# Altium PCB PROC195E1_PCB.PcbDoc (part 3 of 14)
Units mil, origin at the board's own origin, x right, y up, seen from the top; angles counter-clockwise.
Board outline 3110.24 x 2500 mil, 10 copper layers (Top Layer, L02_GND1, L03_SIG1, L04_GND2, L05_PWR1, L06_PWR2, L07_GND3, L08_SIG2, L09_GND4, Bottom Layer), stack 66.407 mil thick; 571 components, 538 nets, 6726 pads, 1286 vias.
Unrouted connection lines stored in the file: 4.
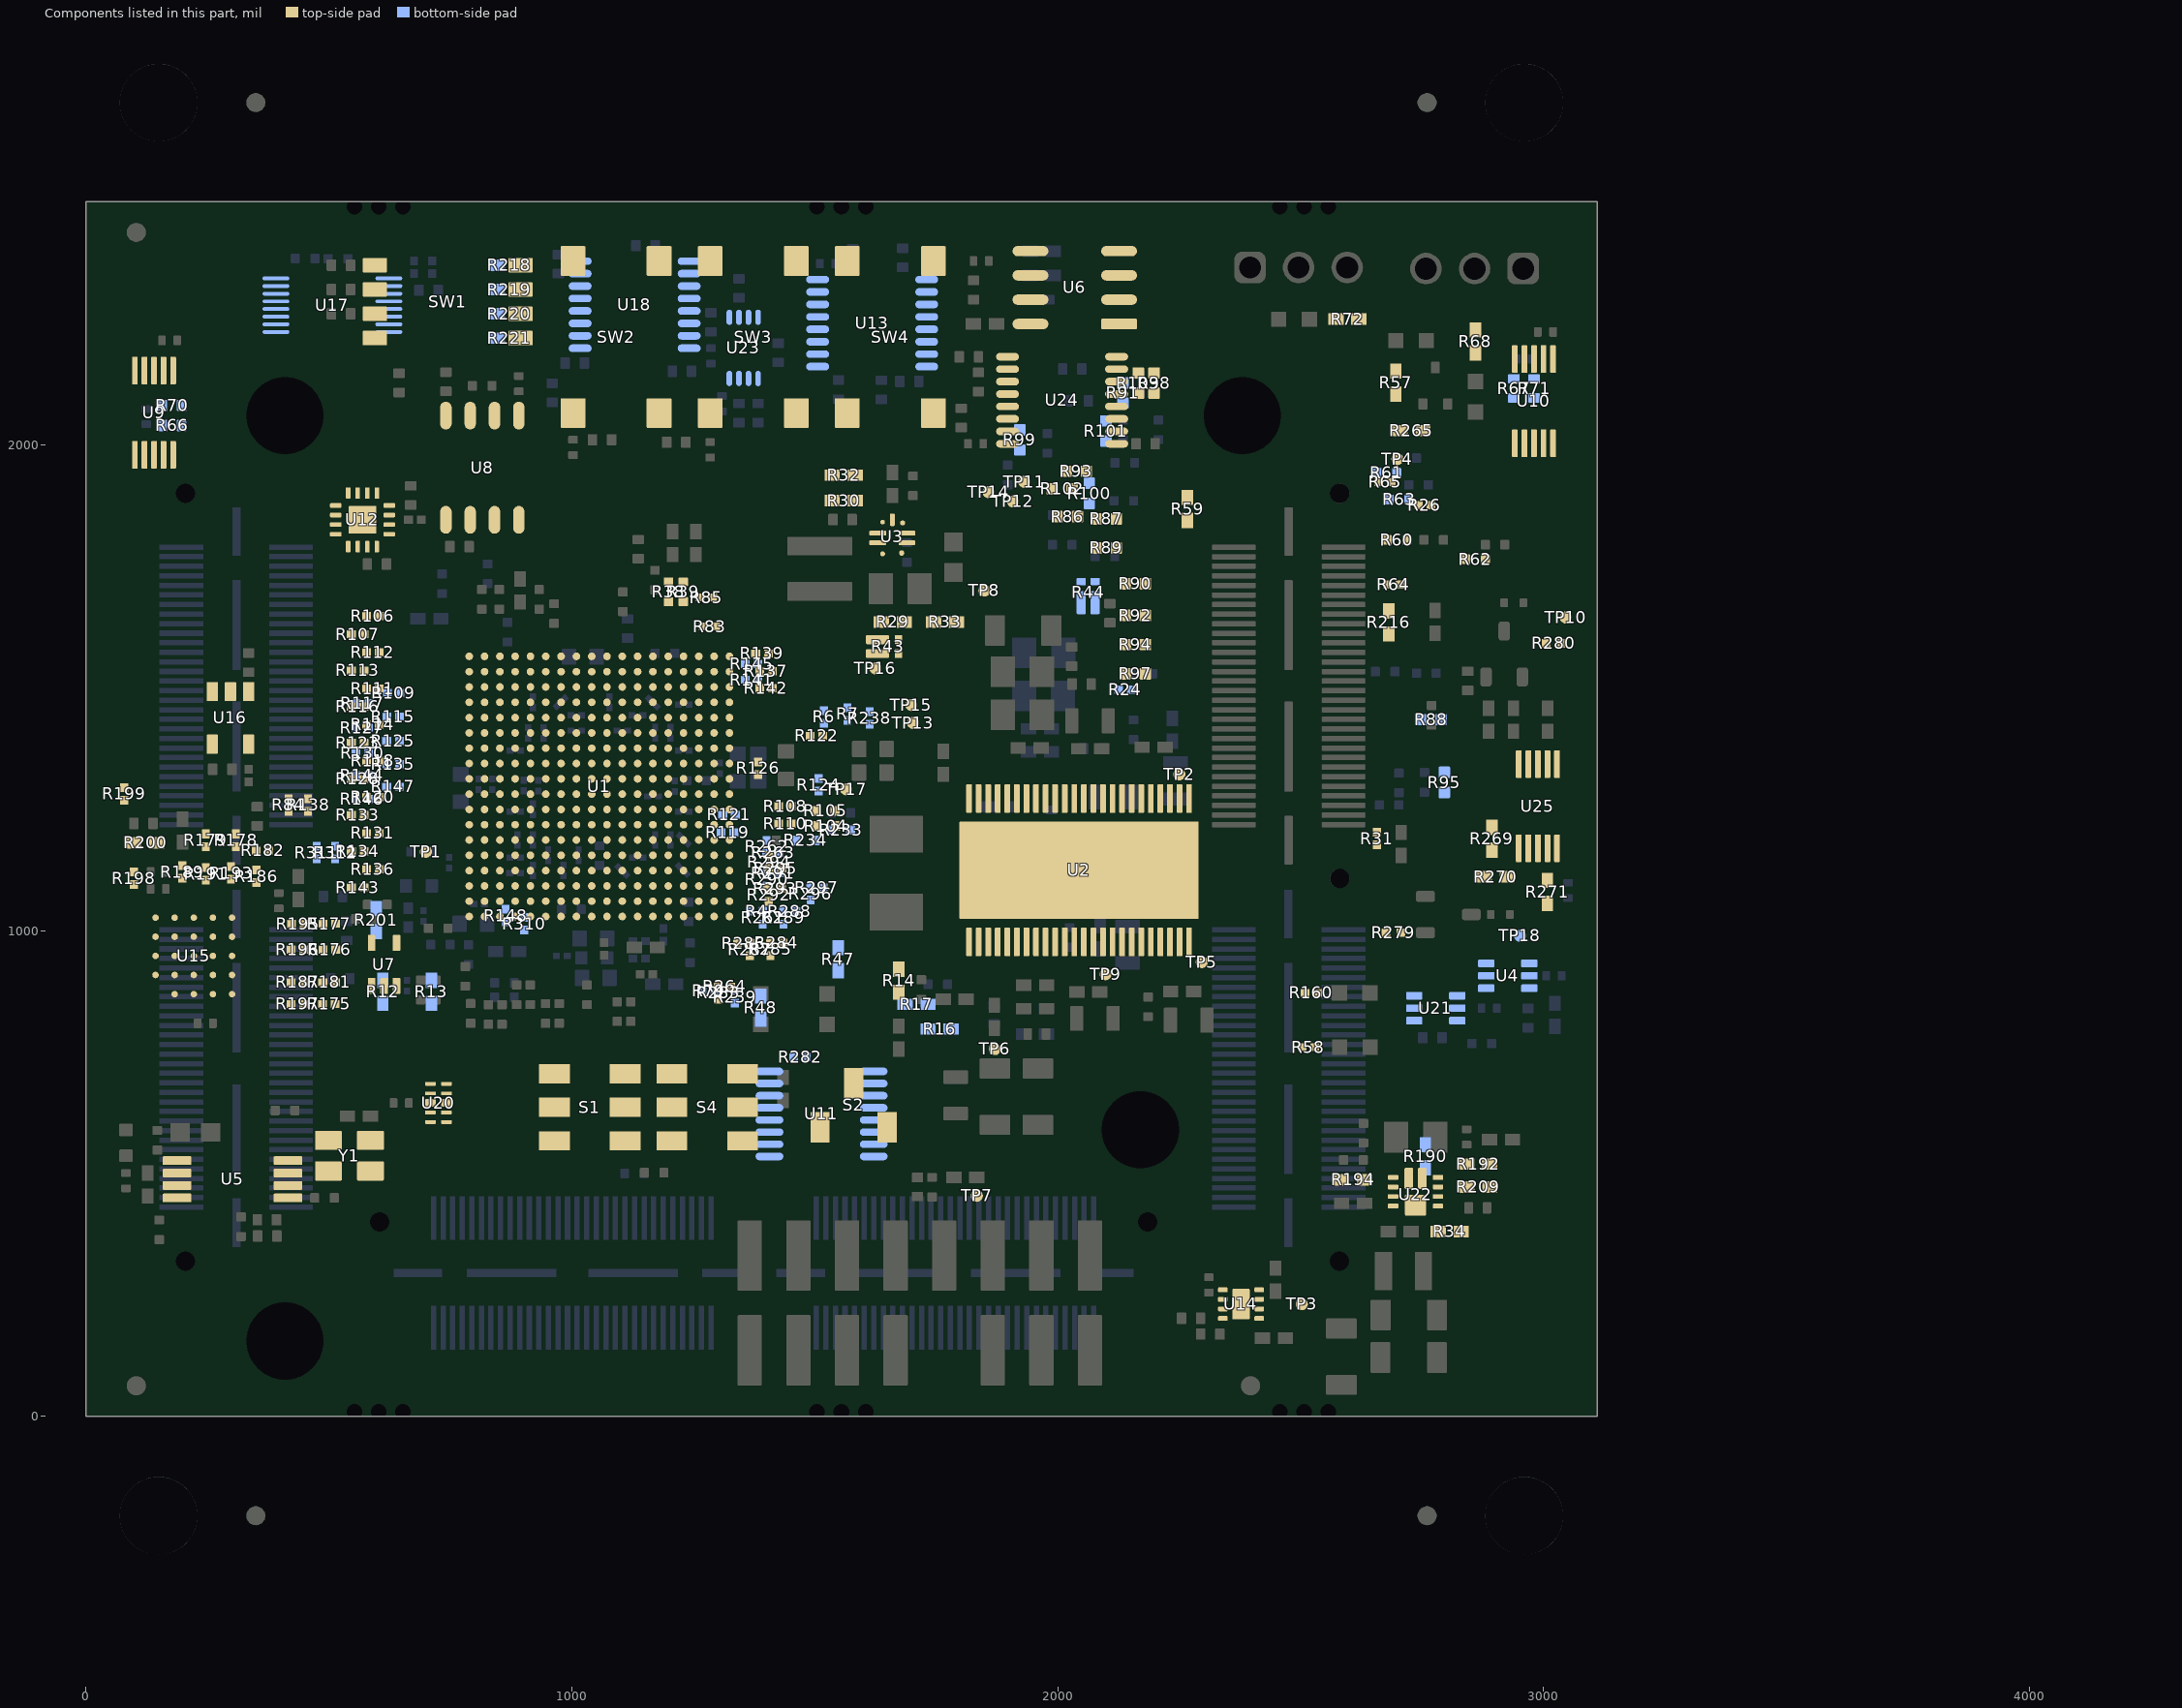
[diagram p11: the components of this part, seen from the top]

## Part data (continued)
R4 R6 R7 R26 R31 R64 R79 R83 R84 R85 R108 R110 R119 R121 R122 R124 R126 R137 R138 R139 R141 R142 R145 R148 R199 R238 R239 R261 R262 R263 R264 R282 R283 R284 R285 R286 R287 R288 R289 R290 R291 R292 R293 R294 R295 R296 R297 R310 R311 R312: library part CMP-0065361-1, "RES, 0, 5%, .05 W, AEC-Q200 Grade 0, 0201", Manufacturer=Panasonic, Power_W=50mW, Supplier Part Number 1=P15979CT-ND, TempCo=ppm/C, Tolerance_%=5%, Value2=.05W, Value_Code=0000, ValueDisplayed=0
R12 R16 R29 R33 R271: library part CMP-0077731-1, "RES, 10.0 k, 1%, 0.063 W, AEC-Q200 Grade 0, 0402", Manufacturer="Yageo America", Power_W=63mW, Supplier Part Number 1=YAG3436CT-ND, TempCo="100 ppm/C", Tolerance_%=1%, Value2=0.063W, Value_Code=10k0, ValueDisplayed=10.0k
R13: library part CMP-0026240-2, "RES, 2.67 k, 1%, 0.063 W, AEC-Q200 Grade 0, 0402", Manufacturer=Vishay-Dale, Power_W=63mW, Supplier Part Number 1=541-2.67KLCT-ND, TempCo="100 ppm/C", Tolerance_%=1%, Value2=0.063W, Value_Code=2k67, ValueDisplayed=2.67k
R14: library part CMP-0078193-1, "RES, 1.0 k, 5%, 0.1 W, AEC-Q200 Grade 0, 0402", Manufacturer=Panasonic, Power_W=100mW, Supplier Part Number 1=P1.0KJCT-ND, TempCo="200 ppm/C", Tolerance_%=5%, Value2=0.1W, Value_Code=1k00, ValueDisplayed=1.0k
R17: library part CMP-0026920-5, "RES, 3.9 k, 5%, 0.063 W, AEC-Q200 Grade 0, 0402", Manufacturer=Vishay-Dale, Power_W=63mW, Supplier Part Number 1=541-3.9KJCT-ND, TempCo="200 ppm/C", Tolerance_%=5%, Value2=0.063W, Value_Code=3k90, ValueDisplayed=3.9k
R24 R65 R106 R107 R109 R111 R112 R113 R114 R115 R116 R117 R118 R120 R123 R125 R127 R128 R130 R131 R133 R134 R135 R136 R143 R144 R146 R147 R186 R187 R189 R191 R193 R195 R196 R197 R198: library part CMP-0027500-1, "RES, 22.0, 1%, 0.05 W, 0201", Manufacturer="Yageo America", Power_W=50mW, Supplier Part Number 1=YAG2518CT-ND, TempCo="200 ppm/C", Tolerance_%=1%, Value2=0.05W, Value_Code=22R0, ValueDisplayed=22.0
R30 R32 R201: library part CMP-0026823-3, "RES, 100 k, 5%, 0.063 W, AEC-Q200 Grade 0, 0402", Manufacturer=Vishay-Dale, Power_W=63mW, Supplier Part Number 1=541-100KJCT-ND, TempCo="200 ppm/C", Tolerance_%=5%, Value2=0.063W, Value_Code=100k
R34: library part CMP-0026280-2, "RES, 301 k, 1%, 0.063 W, AEC-Q200 Grade 0, 0402", Manufacturer=Vishay-Dale, Power_W=63mW, Supplier Part Number 1=541-301KLCT-ND, TempCo="100 ppm/C", Tolerance_%=1%, Value2=0.063W, Value_Code=301k
R38 R39 R60 R61 R62 R63: library part CMP-0122104-1, "33 Ohms ±5% 0.1W, 1/10W Chip Resistor 0402 (1005 Metric) Automotive AEC-Q200 Thick Film", Digikey Part Number=P33JCT-ND, Manufacturer=Panasonic, Mouser Part Number=667-ERJ-2GEJ330X, Operating Temperature Range="-55°C to +155°C", Power_W=100mW, TempCo=200ppm/°C, Tolerance_%=5%
R43 R44: library part CMP-0122058-1, "Res Metal Foil 0306 0.01 Ohm 1% 0.25W(1/4W) ±50ppm/C Epoxy Resin Wide Terminal SMD T/R", Digikey Part Number=FC4L16R010FERCT-ND, Manufacturer=Ohmite, Mouser Part Number=588-FC4L16R010FER, Operating Temperature Range="-40°C to +125°C", Power_W=250mW, TempCo=50ppm/°C, Tolerance_%=1%
R47 R48: library part CMP-0026854-5, "RES, 1.2 k, 5%, 0.063 W, AEC-Q200 Grade 0, 0402", Manufacturer=Vishay-Dale, Power_W=63mW, Supplier Part Number 1=541-1.2KJCT-ND, TempCo="200 ppm/C", Tolerance_%=5%, Value2=0.063W, Value_Code=1k20, ValueDisplayed=1.2k
R57 R68 R72: library part CMP-0025998-3, "RES, 130, 1%, 0.063 W, AEC-Q200 Grade 0, 0402", Manufacturer=Vishay-Dale, Power_W=63mW, Supplier Part Number 1=541-130LCT-ND, TempCo="100 ppm/C", Tolerance_%=1%, Value2=0.063W, Value_Code=130R, ValueDisplayed=130
R58 R160: library part CMP-0027222-1, "RES, 300, 5%, 0.05 W, 0201", Manufacturer="Yageo America", Power_W=50mW, Supplier Part Number 1=603-RC0201JR-7D300RL, TempCo="200 ppm/C", Tolerance_%=5%, Value2=0.05W, Value_Code=300R, ValueDisplayed=300
R59 R216: library part CMP-0025951-3, "RES, 100, 1%, 0.063 W, AEC-Q200 Grade 0, 0402", Manufacturer=Vishay-Dale, Power_W=63mW, Supplier Part Number 1=541-100LCT-ND, TempCo="100 ppm/C", Tolerance_%=1%, Value2=0.063W, Value_Code=100R, ValueDisplayed=100
R66 R67 R70 R71: library part CMP-0122043-1, "Res General Purpose Thick Film 0402 10 Ohm 1% 1/16W ±200ppm/°C Molded SMD Paper T/R", Digikey Part Number=311-10.0LRCT-ND, Manufacturer=Yageo, Mouser Part Number=603-RC0402FR-0710RL, Operating Temperature Range="-55°C to +155°C", Power_W=63mW, TempCo=200ppm/°C, Tolerance_%=1%
R86 R87 R88 R89 R90 R91 R92 R93 R94 R95 R97 R98 R99 R100 R101 R102 R103: library part CMP-0097633-1, "10 Ohms ±1% 0.125W, 1/8W Chip Resistor 0402 (1005 Metric) Automotive AEC-Q200 Thick Film", Digikey Part Number=541-RCC040210R0FKEDCT-ND, Manufacturer="Vishay Dale", Mouser Part Number=71-RCC040210R0FKED, Operating Temperature Range="-55°C to +155°C", Power_W=125mW, TempCo=100ppm/°C, Tolerance_%=1%
R104 R105 R233 R234: library part CMP-0042990-1, "Res Thick Film 0402 1.5K Ohm 5% 1/10W ±200ppm/°C Molded SMD Punched Carrier T/R", Digikey Part Number=P1.5KJCT-ND, Manufacturer=Panasonic, Mouser Part Number=667-ERJ-2GEJ152X, Octopart Part Number=cecc048b4d5c110b, Operating Temperature Range="-55°C to +155°C", Power_W=100mW, TempCo=200ppm/°C, Tolerance_%=5%, Voltage=50V
R175 R176 R177 R178 R179 R181 R182: library part CMP-0027732-1, "RES, 49.9 k, 1%, 0.05 W, 0201", Manufacturer="Yageo America", Power_W=50mW, Supplier Part Number 1=YAG2701CT-ND, TempCo="200 ppm/C", Tolerance_%=1%, Value2=0.05W, Value_Code=49k9, ValueDisplayed=49.9k
R190: library part CMP-0026102-2, "RES, 1.05 M, 1%, 0.063 W, AEC-Q200 Grade 0, 0402", Manufacturer=Vishay-Dale, Power_W=63mW, Supplier Part Number 1=541-1.05MLCT-ND, TempCo="100 ppm/C", Tolerance_%=1%, Value2=0.063W, Value_Code=1M05, ValueDisplayed=1.05M
R192: library part CMP-0026187-2, "RES, 23.7 k, 1%, 0.063 W, AEC-Q200 Grade 0, 0402", Manufacturer=Vishay-Dale, Power_W=63mW, Supplier Part Number 1=541-23.7KLCT-ND, TempCo="100 ppm/C", Tolerance_%=1%, Value2=0.063W, Value_Code=23k7, ValueDisplayed=23.7k
R194: library part CMP-0026046-3, "RES, 174 k, 1%, 0.063 W, AEC-Q200 Grade 0, 0402", Manufacturer=Vishay-Dale, Power_W=63mW, Supplier Part Number 1=541-174KLCT-ND, TempCo="100 ppm/C", Tolerance_%=1%, Value2=0.063W, Value_Code=174k
R200 R218 R219 R220 R221 R265 R269 R270: library part CMP-0026657-1, "RES, 1.00 k, 1%, 0.1 W, 0402", Manufacturer=Panasonic, Power_W=100mW, Supplier Part Number 1=P1.00KLCT-ND, TempCo="100 ppm/C", Tolerance_%=1%, Value2=0.1W, Value_Code=1k00, ValueDisplayed=1.00k
R209: library part CMP-0025973-3, "RES, 118 k, 1%, 0.063 W, AEC-Q200 Grade 0, 0402", Manufacturer=Vishay-Dale, Power_W=63mW, Supplier Part Number 1=541-118KLCT-ND, TempCo="100 ppm/C", Tolerance_%=1%, Value2=0.063W, Value_Code=118k
R279 R280: library part CMP-2002-00487-3, "Chip Resistor, 220 Ohm, +/- 5%, 100 mW, -55 to 155 degC, 0402 (1005 Metric), RoHS, Tape and Reel", Case Code (Imperial)=0402, Case Code (Metric)=1005, Manufacturer="Basic Passives", Max Operating Temperature="155 degC", Min Operating Temperature="-55 degC", Package Quantity=10000, Power Rating="100 mW", Resistance="220 Ohm", Tolerance=5%, Voltage Rating="50 V"
S1 S4: library part CMP-0002233-1, "Switch, Dual SPDT,  2 Pos, 0.1A, 6VDC, SMD", CurrentRating_mA=100A, Manufacturer="Copal Electronics", Supplier Part Number 1=CASD20JCT-ND
S2: library part CMP-0002139-2, "Switch, Slide, SPDT  100mA, SMT", CurrentRating_mA=100A, Manufacturer="Copal Electronics", Supplier Part Number 1=CAS120JCT-ND
SW1: library part CMP-0093176-1, "Dip Switch SPST 4 Position Surface Mount Slide (Standard) Actuator 25mA 24VDC", Coil Resistance_ohm=100mΩ, Contact Current Rating=25mA, Digikey Part Number=732-3854-1-ND, Manufacturer=Wurth, Mouser Part Number=710-416131160804, Operating Temperature Range="-40°C to +85°C"
SW2 SW3 SW4: library part CMP-0097324-1, "Switch Tactile N.O. SPST Round Button Gull Wing 0.05A 12VDC 1000000Cycles 1.57N SMD Reel", Coil Resistance_ohm=100mΩ, Contact Current Rating=50mA, Digikey Part Number=732-7005-1-ND, Manufacturer="Wurth Electronics", Mouser Part Number=710-430182050816, Operating Force=160gf, Operating Temperature Range="-40°C to +85°C"
TP1 TP2 TP3 TP4 TP5 TP6 TP7 TP8 TP9 TP10 TP11 TP12 TP13 TP14 TP15 TP16 TP17 TP18: library part CMP-0078143-3, "TEST POINT.  No entry in BOM.", Manufacturer=N/A
U1: library part CMP-0121930-1, Manufacturer="Texas Instruments", Operating Temperature Range=to
U2: library part CMP-0095884-1, "Power Management IC For Safety-Relevant Applications HTSSOP48 5 Outputs 4 LDO and 1 Synchronous Buck-Boost Regulator", Manufacturer="Texas Instruments", Max Supply Voltage=28V, Min Supply Voltage=2.3V, Operating Temperature Range="-40°C to +150°C"
U3: library part CMP-0093448-1, "3-V to 18-V, High Efficiency and Low IQ Buck Converter in QFN HR  Package with 165C Junction temperature", Manufacturer="Texas Instruments", Max Supply Voltage=18V, Min Supply Voltage=3V, Nominal Supply Current=8mA, Operating Temperature Range="-55°C to +165°C", Output Voltage=0.4-5.5V, Switching Frequency=1/2.5MHz
U4 U21: library part CMP-0051216-3, "Single 3-Input Positive-AND Gate, DCK0006A (SOT-SC70-6)", F @ Nom Voltage(Max)(Mhz)=150, Generic Part Number=SN74LVC1G11, ICC @ Nom Voltage(Max)(mA)=0.01, Manufacturer="Texas Instruments", Operating Temperature Range="-40 to 125,-40 to 85 C", Rating=Catalog, tpd @ Nom Voltage(Max)(ns)=20,7.8,6.2,4.6, Voltage(Nom)(V)=1.8,2.5,3.3,5
U5: library part CMP-0096980-1, "1.8-V, 2.5-V, and 3.3-V LVCMOS Clock Buffer Family", Digikey Part Number=296-LMK1C1104PWRCT-ND, Manufacturer="Texas Instruments", Max Supply Voltage=3.465V, Min Supply Voltage=1.71V, Mouser Part Number=595-LMK1C1104PWR, Nominal Supply Current=25-33000uA, Operating Temperature Range="-40°C to +125°C"
U6: library part CMP-0122130-1, "EEPROM Serial-I2C 1M-bit 128K x 8 2.5V/3.3V/5V 8-Pin SOIC N T/R", Digikey Part Number=CAT24M01WI-GT3OSCT-ND, Frequency_Fixed=1MHz, Manufacturer="ON Semi", Max Supply Voltage=5.5V, Min Supply Voltage=1.8V, Mouser Part Number=863-CAT24M01WI-GT3, Nominal Supply Current=1-5mA, Operating Temperature Range="-40°C to +85°C"
U7: library part CMP-0051718-3, "Single Power Supply BUFFER Logic Level Shifter (no enable), DCK0005A (SOT-SC70-5)", F @ Nom Voltage(Max)(Mhz)=50, Generic Part Number=SN74LV1T34, ICC @ Nom Voltage(Max)(mA)=0.01, Manufacturer="Texas Instruments", Operating Temperature Range(C)="-40 to 125", Rating=Catalog, tpd @ Nom Voltage(Max)(ns)=14.5,9.5,8.0,6.5, Voltage(Nom)(V)=1.8,2.5,3.3,5.5
U8: library part CMP-0078516-1, "Remote and Local Temperature Sensor with N-Factor and Series-R Correction in MSOP-8, D0008A (SOIC-8)", Alternate Manufacturer="Texas Instruments", Alternate PartNumber=TMP411AD
U9 U10: library part CMP-0098432-1, "Current Sense Amplifier 1 Circuit 10-VSSOP", Digikey Part Number=296-INA228AIDGSTCT-ND, Input Bias Current=0.01uA, Input Offset Voltage=1mV, Manufacturer="Texas Instruments", Max Supply Voltage=5.5V, Min Supply Voltage=2.7V, Mouser Part Number=595-INA228AIDGST, Nominal Supply Current=640uA, Operating Temperature Range="-40°C to +125°C"
U11: library part CMP-0041147-1, "High-Speed, Single-Supply, Rail-to-Rail Operational Amplifier MicroAmplifier(TM) Series, 2.7 to 5.5 V, -55 to 150 degC, 16-pin SOP (DBQ16), Green (RoHS & no Sb/Br)", Manufacturer="Texas Instruments", Total Supply Voltage(Max)(+5V is 5, +/-5V is 10)=5.5, Total Supply Voltage(Min)(+5V is 5, +/-5V is 10)=2.7
U12: library part CMP-0043157-2, "Low-Voltage 8-Bit I2C and SMBus I/O Expander, 1.65 to 5.5 V, -40 to 85 degC, 16-pin QFN (RGT), Green (RoHS & no Sb/Br)", 5V Tolerant I/O=Yes, Manufacturer="Texas Instruments", Max Frequency(kHz)=400
U13 U18 U24: library part CMP-0076540-1, "4-Bit One-of-2 FET Multiplexer/Demultiplexer 2.5-V/3.3-V Low-Voltage, High-Bandwidth Bus Switch, PW0016A (TSSOP-16)", Alternate Manufacturer="Texas Instruments"
U14: library part CMP-0122128-1, "IC LOAD SWITCH 6A 8WSON", Digikey Part Number=296-34943-1-ND, Manufacturer="Texas Instruments", Max Supply Voltage=5.7V, Min Supply Voltage=2.5V, Mouser Part Number=595-TPS22965DSGT, Nominal Supply Current=20-50uA, On State Resistance=16mΩ, Operating Temperature Range="-40°C to +105°C", Output Voltage=0.8-5.7V
U15: library part CMP-0120691-1, "FLASH Memory IC 256Mbit SPI - Octal I/O 133 MHz 6 ns 24-TFBGA (6x8)", Digikey Part Number=706-IS25LX256-LHLE-ND, Frequency_Fixed=133MHz, Manufacturer=ISSI, Max Supply Voltage=3.6V, Min Supply Voltage=2.7V, Mouser Part Number=870-IS25LX256-LHLE, Nominal Supply Current=0.13-48mA, Operating Temperature Range="-40°C to +105°C"
U16: library part CMP-0051588-2, "Single 2-Input Positive-AND Gate, DBV0005A, LARGE T&R", Alternate Manufacturer="Texas Instruments", F @ Nom Voltage(Max)(Mhz)=150, Generic Part Number=SN74LVC1G08, ICC @ Nom Voltage(Max)(mA)=0.01, Operating Temperature Range(C)="-40 to 125,-40 to 85", Rating=Catalog, tpd @ Nom Voltage(Max)(ns)=4.5,6,4,5, Voltage(Nom)(V)=1.8,2.5,3.3,5
U17: library part CMP-0066446-2, "4-Bit Dual-Supply Bus Transceiver with Configurable Voltage-Level Shifting and 3-State Outputs, DGV0016A (TVSOP-16)", Alternate Manufacturer="Texas Instruments"
U20: library part CMP-0860454-1, "5-V Low-Leakage-Current, 2:1, 2-Channel Precision Analog Switch, DQA0010A (USON-10)", Alternate Manufacturer="Texas Instruments", Operating Temperature Range="-40 to 125 C", Rating=Catalog
U22: library part CMP-0074067-1, "12.6-V, 7-A Fully-Integrated Synchronous Boost Converters in 2.0-mm x 2.5-mm VQFN Package, RNR0011A (VQFN-HR-11)", Alternate Manufacturer="Texas Instruments", Alternate PartNumber=TPS61089RNRT
U23: library part CMP-0051981-2, "TRIPLE SCHMITT-TRIGGER BUFFER, DCU0008A (VSSOP-8)", F @ Nom Voltage(Max)(Mhz)=150, Generic Part Number=SN74LVC3G17, ICC @ Nom Voltage(Max)(mA)=0.01, Manufacturer="Texas Instruments", Operating Temperature Range="-40 to 125 C", Rating=Catalog, tpd @ Nom Voltage(Max)(ns)=9.2,6.2,5.4,4.1, Voltage(Nom)(V)=1.8,2.5,3.3,5
U25: library part CMP-0122044-1, "ESD-Protected, Low Capacitance, 2-Channel, 2:1 Switch, With Powered-off Protection", Digikey Part Number=296-48347-1-ND, Manufacturer="Texas Instruments", Max Supply Voltage=4.3V, Min Supply Voltage=3V, Mouser Part Number=595-TMUX154EDGSR, Nominal Supply Current=1uA, On State Resistance=6Ω, Operating Temperature Range="-40°C to +85°C"
Y1: library part CMP-0122114-1, "25 MHz XO (Standard) CMOS Oscillator 3.3V Standby (Power Down) 4-SMD, No Lead", Digikey Part Number=1923-831055678CT-ND, Frequency Stability=25ppm, Frequency_Fixed=25MHz, Load Capacitance=15pF, Manufacturer="Wurth Electronics", Max Supply Current=12mA, Max Supply Voltage=3.63V, Min Supply Voltage=2.97V, Mouser Part Number=710-831055678, Operating Temperature Range="-40°C to +85°C"
ZZ1: library part CMP-0003616-3
ZZ2: library part CMP-0077236-1
ZZ3: library part CMP-0077237-1
ZZ4: library part CMP-0077238-1

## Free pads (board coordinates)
  round 3 on Mech16: 1(0,0) 1(0,0) 1(0,2276.49) 1(0,2276.49) 1(2755.9,2276.49) 1(2755.9,2276.49) 1(2755.9,0) 1(2755.9,0) 1(2915,880) 1(2915,880) 1(2915,880) 1(2925,870) 1(2925,870) 1(2925,890) 1(2925,890) 1(2936,423) 1(2936,423) 1(2943,416) 1(2943,416) 1(2945,416) 1(2945,416) 1(2945,416) 1(2945,416) 1(2945,423) 1(2945,445) 1(2945,445) 1(2950,445) 1(2950,445) 1(2952,423) 1(2952,423) 1(2953,423) 1(2953,423) 1(2957,445) 1(2967,781) 1(2967,781) 1(2967,781) 1(2970,880) 1(2970,880) 1(2977,771) 1(2977,771) 1(2977,791) 1(2977,791) 1(2999,781) 1(2999,781) 1(2999,855) 1(2999,855) 1(3040,1210) 1(3040,1210) 1(3040,1210) 1(3042,975) 1(3042,975) 1(3042,1076) 1(3050,1200) 1(3050,1200) 1(3050,1220) 1(3050,1220) 1(3055,880) 1(3055,880) 1(3055,945) 1(3055,945) 1(3055,975) 1(3055,975) 1(3055,975) 1(3095,855) 1(3095,855) 1(3110,1170) 1(3110,1170) 1(3110,1210) 1(3110,1210) 1(3120,1170) 1(3120,1170) 1(3137.87,855) 1(3140,830) 1(3140,830) 1(3140,929) 1(3228,975) 1(3335,1170) 1(3335,1170) 1(3335,1225) 1(3335,1225) 1(3361,830) 1(3635,1225) 1(4040,-80) 1(4040,-80) 1(4050,-90) 1(4050,-90) 1(4050,-90) 1(4050,-30) 1(4060,-80) 1(4060,-80)
  round 5 on Mech16: 1(49.97,2225.98) 1(49.97,2225.98) 1(49.97,21.03) 1(49.98,21.03) 1(162.95,-222.97) 1(162.95,-222.97) 1(162.95,-144.97) 1(162.95,-144.97) 1(178.95,-144.97) 1(178.95,-144.97) 1(240.95,-111.97) 1(240.95,21.03) 1(240.95,21.03) 1(241.45,-111.95) 1(341.36,-467.81) 1(341.36,-467.81) 1(341.36,-231.59) 1(341.36,-231.59) 1(341.36,-222.97) 1(341.36,-222.97) 1(517,482.84) 1(522.16,488) 1(1263.8,-467.81) 1(1263.8,-467.81) 1(1263.8,-263.09) 1(1263.8,-263.09) 1(1358.29,-467.81) 1(1358.29,-467.81) 1(1358.29,-263.09) 1(1358.29,-263.09) 1(2016.27,2225.98) 1(2016.27,2225.99) 1(2399.24,-467.81) 1(2399.24,-467.81) 1(2399.24,-231.59) 1(2399.24,-231.59) 1(2399.24,-222.97) 1(2399.24,-222.97) 1(2404.95,-222.97) 1(2404.95,-222.97) 1(2502.95,-112.97) 1(2502.95,-15.38) 1(2502.95,-15.38) 1(2502.95,21.03) 1(2502.95,21.03) 1(2503.45,-112.97) 1(2565.95,-143.97) 1(2565.95,-143.97) 1(2581.95,-222.97) 1(2581.95,-222.97) 1(2581.95,-143.97) 1(2581.95,-143.97) 1(3153.26,-454.97) 1(3153.26,-454.97) 1(3153.26,21.03) 1(3153.26,21.03) 1(4148.54,-454.97) 1(4148.54,-454.97) 1(4148.54,-222.87) 1(4148.54,-222.87) 1(4213.95,2225.99) 1(4213.95,2225.99) 1(4213.95,-222.87) 1(4213.95,-222.87)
